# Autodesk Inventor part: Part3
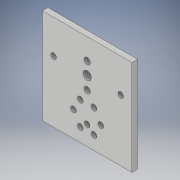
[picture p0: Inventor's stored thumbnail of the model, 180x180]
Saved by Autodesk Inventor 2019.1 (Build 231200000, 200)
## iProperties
Created: 2018-09
Part Number: Part3
Material: Generic
Document SubType Name: Modeling
Designer: drawing
Density: 1 g/cm^3
Appearance: Default
Author: drawing
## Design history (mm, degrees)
sketch "Sketch1"
  geometry: L1 (0, 0)-(101.6, 0); L2 (101.6, 0)-(101.6, 107.95); L3 (101.6, 107.95)-(0, 107.95); L4 (0, 107.95)-(0, 0)
  constraints: 8 end point, 2 parallel, 1 horizontal, 1 perpendicular
  dimensions: "d0" = 101.6 distance of L3.end L2.end; "d1" = 107.95 distance of L2.end L1.end
extrude "Extrusion1" new body sketch "Sketch1" distance "d2" = 6.35; taper "d3" = 0 deg
sketch "Sketch2"
  geometry: L1 (101.6, 107.95)-(0, 107.95) reference; L2 (101.6, 0)-(101.6, 107.95) reference; L3 (0, 0)-(101.6, 0) reference; 3 further points
  constraints: 2 midpoint, 1 vertical alignment
  dimensions: "d31" = 38.1 distance from line of L1 point (50.8, 69.85)
hole "Hole1" sketch "Sketch2" at (50.8, 69.85) diameter "d4" = 9.525; stored, may be unused: countersink angle "d8" = 82 deg, drill point angle "d10" = 118 deg; dims "d5" = 19.05, "d6" = 9.525, "d7" = 6.35, "d9" = 19.05
sketch "Sketch3"
  geometry: L1 (101.6, 107.95)-(0, 107.95) reference; L2 (0, 107.95)-(0, 0) reference; C1 r 4.763 at (50.8, 69.85) reference; 2 further points
  constraints: 2 horizontal alignment
  dimensions: "d12" = 12.7 distance from line of L2 point (12.7, 69.85); "d15" = 76.2 distance of point (12.7, 69.85) point (88.9, 69.85)
hole "Hole2" sketch "Sketch3" at (12.7, 69.85), (88.9, 69.85) diameter "d21" = 3.175; stored, may be unused: countersink angle "d25" = 82 deg, drill point angle "d27" = 118 deg; dims "d22" = 19.05, "d23" = 6.35, "d24" = 3.175, "d26" = 19.05
sketch "Sketch4"
  geometry: C1 r 4.763 at (50.8, 69.85) reference; 2 further points
  constraints: 1 vertical alignment
  dimensions: "d39" = 48 distance of C1.centre point (50.8, 21.85)
hole "Hole3" sketch "Sketch4" at (50.8, 21.85) diameter "d32" = 6.35; stored, may be unused: countersink angle "d36" = 82 deg, drill point angle "d38" = 118 deg; dims "d33" = 19.05, "d34" = 9.525, "d35" = 6.35, "d37" = 19.05
sketch "Sketch6"
  geometry: C1 r 4.763 at (-50.8, 69.85) reference; 3 further points
  constraints: 2 vertical alignment
  dimensions: "d52" = 28.575 distance of point (-50.8, 84.138) point (-50.8, 55.562); "d53" = 14.2875 distance of C1.centre point (-50.8, 84.138) (= 0.5 x d52)
hole "Hole5" sketch "Sketch6" at (-50.8, 84.138), (-50.8, 55.562) diameter "d54" = 3.81; stored, may be unused: countersink angle "d58" = 90 deg, drill point angle "d60" = 118 deg; dims "d55" = 19.05, "d56" = 6.35, "d57" = 0.508, "d59" = 19.05
sketch "Sketch7"
  geometry: C1 r 1.905 at (50.8, 84.138) reference; C2 r 1.905 at (50.8, 55.562) reference; 3 further points
  constraints: 2 coincident
hole "Hole6" sketch "Sketch7" at (50.8, 84.138), (50.8, 55.562) diameter "d61" = 3.81; stored, may be unused: countersink angle "d65" = 90 deg, drill point angle "d67" = 118 deg; dims "d62" = 19.05, "d63" = 7.1374, "d64" = 3.5052, "d66" = 19.05
sketch "Sketch8" dims "d68" = 31
  geometry: C1 r 3.175 at (50.8, 21.85) reference; 8 further points
  constraints: 2 horizontal alignment, 1 vertical alignment, 9 other
  dimensions: "d69" = 7 distance of C1.centre point (50.8, 28.85); "d79" = 360 deg dimension on point (50.8, 28.85) point (66.3, 28.85) (derived)
hole "Hole8" sketch "Sketch8" at (66.3, 28.85), (58.55, 42.273), (43.05, 42.273), (35.3, 28.85), (43.05, 15.427), (58.55, 15.427) diameter "d81" = 3.4036; stored, may be unused: countersink angle "d85" = 82 deg, drill point angle "d87" = 118 deg; dims "d82" = 19.05, "d83" = 6.5024, "d84" = 2.9972, "d86" = 12.2936
body "Solid1"
